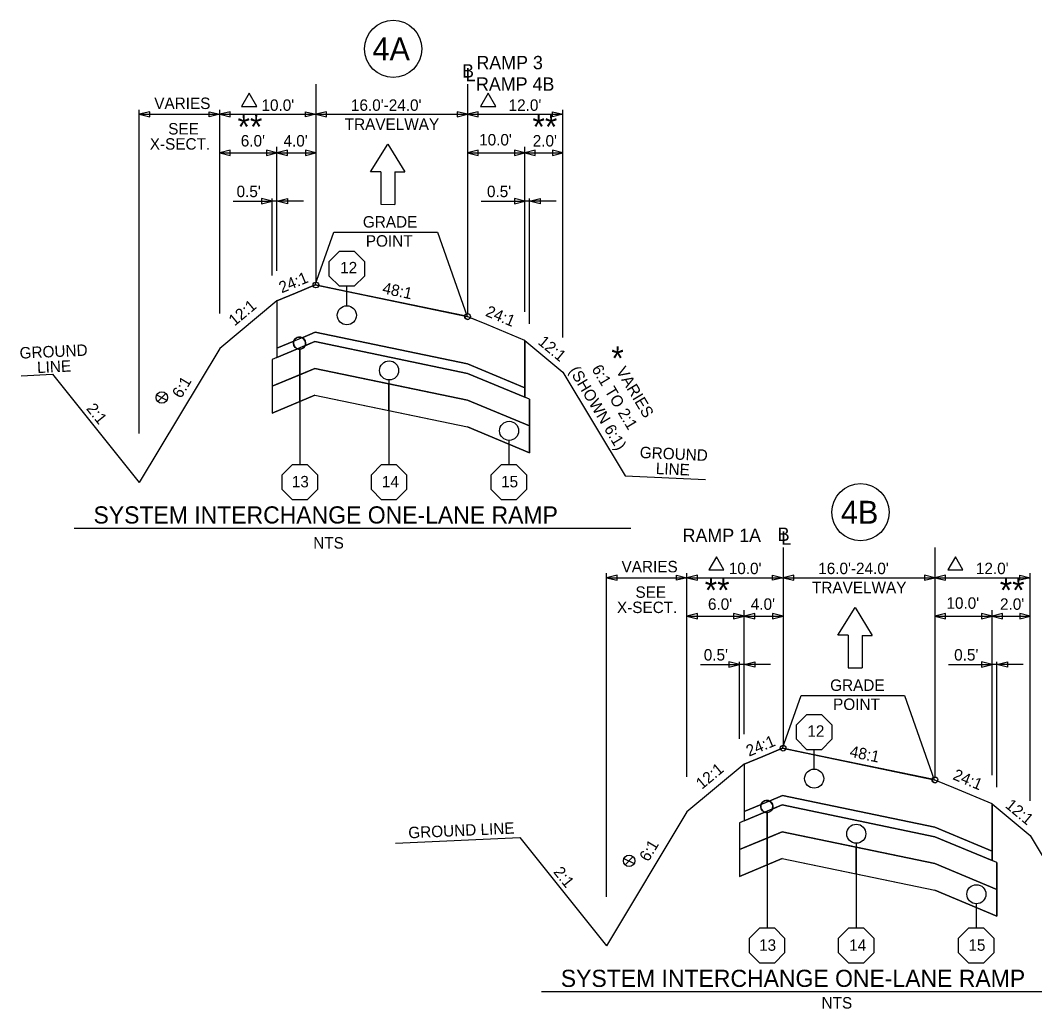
# Model space of a CAD drawing. Extents: x 4932 to 5887, y 4809 to 5473.
# Drawn here: x 5014.7 to 5121, y 5056.1 to 5159.8 of the extents above; entities that cross this region are included whole.
import ezdxf

# ---------------------------------------------------------------- set-up
doc = ezdxf.new("R2010")
doc.units = 0
for name, color, linetype in [('Level 20', 7, 'Continuous'), ('Level 25', 7, 'Continuous'), ('RD_QTY_Miscl_1', 7, 'Continuous'), ('RD_QTY_Miscl_2', 7, 'Continuous'), ('RD_QTY_Miscl_3', 7, 'Continuous'), ('RD_QTY_Miscl_4', 7, 'Continuous'), ('RD_SHT_Typical', 7, 'Continuous'), ('RD_TX_TypSect', 7, 'Continuous'), ('RD_XS_ExGround', 7, 'Continuous'), ('typical_on', 7, 'Continuous')]:
    doc.layers.add(name, color=color, linetype=linetype)

msp = doc.modelspace()

# ---------------------------------------------------------------- linework, layer by layer
at = {"layer": 'Level 20'}
for p, q in [((5051.37, 5143.89), (5053.2, 5146.8)), ((5053.2, 5146.8), (5054.98, 5143.88)), ((5052.47, 5143.89), (5051.37, 5143.89)), ((5052.47, 5143.89), (5052.47, 5140.49)), ((5053.92, 5143.88), (5054.98, 5143.88)), ((5053.92, 5143.88), (5053.92, 5140.48)), ((5052.47, 5140.49), (5053.92, 5140.48)), ((5100.36, 5095.3), (5102.18, 5098.22)), ((5102.18, 5098.22), (5103.97, 5095.29)), ((5101.45, 5095.3), (5100.36, 5095.3)), ((5101.45, 5095.3), (5101.45, 5091.9)), ((5102.91, 5095.29), (5103.97, 5095.29)), ((5102.91, 5095.29), (5102.91, 5091.89)), ((5101.45, 5091.9), (5102.91, 5091.89))]:
    msp.add_line(p, q, dxfattribs=at)
at = {"layer": 'Level 25'}
for p, q in [((5045.58, 5132.05), (5047.52, 5137.58)), ((5047.52, 5137.58), (5058.38, 5137.58)), ((5058.38, 5137.58), (5061.49, 5128.73)), ((5094.57, 5083.46), (5096.51, 5089)), ((5096.51, 5089), (5107.37, 5089)), ((5107.37, 5089), (5110.47, 5080.15))]:
    msp.add_line(p, q, dxfattribs=at)
for centre in [(5053.75, 5156.78), (5102.74, 5108.2)]:
    msp.add_circle(centre, 3, dxfattribs=at)
at = {"layer": 'RD_QTY_Miscl_1'}
for p, q in [((5045.58, 5132.05), (5043.5, 5131.18)), ((5043.5, 5131.18), (5041.56, 5130.37)), ((5041.56, 5130.37), (5041.56, 5125.41)), ((5063.55, 5127.87), (5061.82, 5128.59)), ((5067.55, 5126.21), (5063.55, 5127.87)), ((5041.56, 5125.41), (5043.34, 5126.15)), ((5044.19, 5126.5), (5045.58, 5127.08)), ((5045.58, 5127.08), (5061.55, 5123.76)), ((5067.55, 5121.26), (5067.55, 5126.21)), ((5061.55, 5123.76), (5067.55, 5121.26)), ((5092.49, 5082.6), (5090.55, 5081.79)), ((5094.57, 5083.46), (5092.49, 5082.6)), ((5090.55, 5081.79), (5090.55, 5076.82)), ((5112.54, 5079.29), (5110.81, 5080.01)), ((5093.18, 5077.92), (5094.57, 5078.5)), ((5094.57, 5078.5), (5110.54, 5075.17)), ((5116.54, 5077.62), (5112.54, 5079.29)), ((5090.55, 5076.82), (5092.33, 5077.56)), ((5116.54, 5072.67), (5116.54, 5077.62)), ((5110.54, 5075.17), (5116.54, 5072.67))]:
    msp.add_line(p, q, dxfattribs=at)
for points in [[(5061.26, 5128.78), (5048.89, 5131.36), (5045.58, 5132.05)], [(5110.24, 5080.2), (5097.88, 5082.77), (5094.57, 5083.46)]]:
    msp.add_lwpolyline(points, dxfattribs=at)
for centre in [(5048.89, 5128.85), (5097.88, 5080.27)]:
    msp.add_circle(centre, 1, dxfattribs=at)
for centre, radius, start, end in [((5061.55, 5128.72), 0.3, 168.2319, 334.9662), ((5043.93, 5125.93), 0.63, 65.5928, 159.6453), ((5110.54, 5080.14), 0.3, 168.2319, 334.9662), ((5092.92, 5077.35), 0.63, 65.5928, 159.6453)]:
    msp.add_arc(centre, radius, start, end, dxfattribs=at)
at = {"layer": 'RD_QTY_Miscl_2'}
for p, q in [((5043.34, 5126.15), (5041.56, 5125.41)), ((5045.58, 5127.08), (5044.19, 5126.5)), ((5061.55, 5123.76), (5045.58, 5127.08)), ((5041.56, 5125.41), (5041.56, 5124.43)), ((5041.56, 5124.43), (5043.72, 5125.34)), ((5044.5, 5125.66), (5045.55, 5126.1)), ((5045.55, 5126.1), (5061.55, 5122.76)), ((5067.55, 5121.26), (5061.55, 5123.76)), ((5061.55, 5122.76), (5067.55, 5120.27)), ((5067.55, 5120.27), (5067.55, 5121.26)), ((5094.57, 5078.5), (5093.18, 5077.92)), ((5110.54, 5075.17), (5094.57, 5078.5)), ((5092.33, 5077.56), (5090.55, 5076.82)), ((5093.48, 5077.07), (5094.54, 5077.51)), ((5094.54, 5077.51), (5110.54, 5074.18)), ((5090.55, 5076.82), (5090.55, 5075.85)), ((5090.55, 5075.85), (5092.71, 5076.75)), ((5116.54, 5072.67), (5110.54, 5075.17)), ((5110.54, 5074.18), (5116.54, 5071.68)), ((5116.54, 5071.68), (5116.54, 5072.67))]:
    msp.add_line(p, q, dxfattribs=at)
for centre, start, end in [((5043.93, 5125.93), 159.6453, 250.9378), ((5043.93, 5125.93), 334.3019, 65.5928), ((5092.92, 5077.35), 159.6453, 250.9378), ((5092.92, 5077.35), 334.3019, 65.5928)]:
    msp.add_arc(centre, 0.63, start, end, dxfattribs=at)
at = {"layer": 'RD_QTY_Miscl_3'}
for p, q in [((5043.95, 5125.3), (5043.95, 5122.62)), ((5043.95, 5122.62), (5043.95, 5125.3)), ((5045.55, 5126.1), (5044.5, 5125.66)), ((5061.55, 5122.76), (5045.55, 5126.1)), ((5041.06, 5124.23), (5041.06, 5121.41)), ((5043.95, 5122.62), (5045.55, 5123.29)), ((5041.06, 5121.41), (5043.95, 5122.62)), ((5067.55, 5120.27), (5061.55, 5122.76)), ((5061.55, 5119.95), (5068.05, 5117.25)), ((5068.05, 5120.06), (5067.55, 5120.27)), ((5068.05, 5117.25), (5068.05, 5120.06)), ((5094.54, 5077.51), (5093.48, 5077.07)), ((5110.54, 5074.18), (5094.54, 5077.51)), ((5092.94, 5076.72), (5092.94, 5074.03)), ((5092.94, 5074.03), (5092.94, 5076.72)), ((5090.05, 5075.64), (5090.05, 5072.83)), ((5090.05, 5072.83), (5092.94, 5074.03)), ((5092.94, 5074.03), (5094.54, 5074.7)), ((5116.54, 5071.68), (5110.54, 5074.18)), ((5110.54, 5071.37), (5117.04, 5068.66)), ((5117.04, 5071.47), (5116.54, 5071.68)), ((5117.04, 5068.66), (5117.04, 5071.47))]:
    msp.add_line(p, q, dxfattribs=at)
for points in [[(5043.72, 5125.34), (5041.56, 5124.43), (5041.06, 5124.23)], [(5045.55, 5123.29), (5053.3, 5121.67), (5061.55, 5119.95)], [(5068.05, 5117.25), (5068.05, 5117.25)], [(5092.71, 5076.75), (5090.55, 5075.85), (5090.05, 5075.64)], [(5094.54, 5074.7), (5102.29, 5073.09), (5110.54, 5071.37)], [(5117.04, 5068.66), (5117.04, 5068.66)]]:
    msp.add_lwpolyline(points, dxfattribs=at)
for centre in [(5053.32, 5123.07), (5102.3, 5074.49)]:
    msp.add_circle(centre, 1, dxfattribs=at)
for centre, start, end in [((5043.93, 5125.93), 250.9378, 272.146), ((5043.93, 5125.93), 272.146, 334.3019), ((5092.92, 5077.35), 250.9378, 272.146), ((5092.92, 5077.35), 272.146, 334.3019)]:
    msp.add_arc(centre, 0.63, start, end, dxfattribs=at)
at = {"layer": 'RD_QTY_Miscl_4'}
for p, q in [((5045.55, 5123.29), (5043.95, 5122.62)), ((5053.3, 5121.67), (5045.55, 5123.29)), ((5043.95, 5122.62), (5041.06, 5121.41)), ((5043.95, 5122.62), (5043.95, 5119.81)), ((5043.95, 5119.81), (5043.95, 5122.62)), ((5053.3, 5118.86), (5053.3, 5121.67)), ((5061.55, 5119.95), (5053.3, 5121.67)), ((5053.3, 5121.67), (5053.3, 5118.86)), ((5041.06, 5118.6), (5043.95, 5119.81)), ((5043.95, 5119.81), (5045.55, 5120.48)), ((5045.55, 5120.48), (5053.3, 5118.86)), ((5068.05, 5117.25), (5061.55, 5119.95)), ((5053.3, 5118.86), (5061.55, 5117.14)), ((5068.05, 5114.43), (5068.05, 5117.25)), ((5092.94, 5074.03), (5090.05, 5072.83)), ((5094.54, 5074.7), (5092.94, 5074.03)), ((5092.94, 5074.03), (5092.94, 5071.22)), ((5092.94, 5071.22), (5092.94, 5074.03)), ((5102.29, 5073.09), (5094.54, 5074.7)), ((5102.29, 5070.28), (5102.29, 5073.09)), ((5110.54, 5071.37), (5102.29, 5073.09)), ((5102.29, 5073.09), (5102.29, 5070.28)), ((5092.94, 5071.22), (5094.54, 5071.89)), ((5094.54, 5071.89), (5102.29, 5070.28)), ((5090.05, 5070.02), (5092.94, 5071.22)), ((5117.04, 5068.66), (5110.54, 5071.37)), ((5102.29, 5070.28), (5110.54, 5068.56)), ((5117.04, 5065.85), (5117.04, 5068.66))]:
    msp.add_line(p, q, dxfattribs=at)
for points in [[(5041.06, 5121.41), (5041.06, 5121.41), (5041.06, 5118.6)], [(5061.55, 5117.14), (5065.88, 5115.34), (5068.05, 5114.43)], [(5068.05, 5117.25), (5068.05, 5117.25)], [(5090.05, 5072.83), (5090.05, 5072.83), (5090.05, 5070.02)], [(5110.54, 5068.56), (5114.86, 5066.76), (5117.04, 5065.85)], [(5117.04, 5068.66), (5117.04, 5068.66)]]:
    msp.add_lwpolyline(points, dxfattribs=at)
for centre in [(5065.9, 5116.74), (5114.89, 5068.15)]:
    msp.add_circle(centre, 1, dxfattribs=at)
at = {"layer": 'RD_SHT_Typical'}
for p, q in [((5043.5, 5131.18), (5045.58, 5132.05)), ((5041.56, 5130.37), (5035.56, 5125.38)), ((5041.56, 5130.37), (5043.5, 5131.18)), ((5041.56, 5130.37), (5041.56, 5124.43)), ((5063.55, 5127.87), (5061.49, 5128.73)), ((5067.55, 5126.21), (5063.55, 5127.87)), ((5041.56, 5125.41), (5045.58, 5127.08)), ((5067.55, 5126.21), (5067.55, 5120.27)), ((5067.55, 5126.21), (5071.55, 5122.88)), ((5035.56, 5125.38), (5027.13, 5111.32)), ((5045.55, 5126.1), (5041.05, 5124.22)), ((5041.06, 5124.23), (5041.06, 5118.6)), ((5045.55, 5123.29), (5041.05, 5121.41)), ((5067.55, 5121.26), (5061.55, 5123.76)), ((5018.04, 5122.67), (5027.13, 5111.32)), ((5068.05, 5120.06), (5061.55, 5122.76)), ((5071.55, 5122.88), (5078.07, 5112.01)), ((5045.55, 5120.48), (5041.06, 5118.6)), ((5068.05, 5117.25), (5061.55, 5119.95)), ((5068.05, 5120.06), (5068.05, 5114.43)), ((5068.05, 5114.43), (5061.55, 5117.14)), ((5090.55, 5081.79), (5092.49, 5082.6)), ((5092.49, 5082.6), (5094.57, 5083.46)), ((5090.55, 5081.79), (5084.55, 5076.79)), ((5090.55, 5081.79), (5090.55, 5075.85)), ((5112.54, 5079.29), (5110.47, 5080.15)), ((5090.55, 5076.82), (5094.57, 5078.5)), ((5116.54, 5077.62), (5112.54, 5079.29)), ((5094.54, 5077.51), (5090.04, 5075.64)), ((5116.54, 5077.62), (5116.54, 5071.68)), ((5116.54, 5077.62), (5120.54, 5074.29)), ((5084.55, 5076.79), (5076.11, 5062.73)), ((5090.05, 5075.64), (5090.05, 5070.02)), ((5116.54, 5072.67), (5110.54, 5075.17)), ((5067.03, 5074.09), (5076.11, 5062.73)), ((5094.54, 5074.7), (5090.04, 5072.83)), ((5117.04, 5071.47), (5110.54, 5074.18)), ((5120.54, 5074.29), (5128.02, 5061.81)), ((5094.54, 5071.89), (5090.05, 5070.02)), ((5117.04, 5068.66), (5110.54, 5071.37)), ((5117.04, 5071.47), (5117.04, 5065.85)), ((5117.04, 5065.85), (5110.54, 5068.56))]:
    msp.add_line(p, q, dxfattribs=at)
for points in [[(5045.58, 5132.05), (5061.49, 5128.73)], [(5045.58, 5127.08), (5061.55, 5123.76)], [(5045.55, 5126.1), (5061.55, 5122.76)], [(5045.55, 5123.29), (5061.55, 5119.95)], [(5045.55, 5120.48), (5061.55, 5117.14)], [(5094.57, 5083.46), (5110.47, 5080.15)], [(5094.57, 5078.5), (5110.54, 5075.17)], [(5094.54, 5077.51), (5110.54, 5074.18)], [(5094.54, 5074.7), (5110.54, 5071.37)], [(5094.54, 5071.89), (5110.54, 5068.56)]]:
    msp.add_lwpolyline(points, dxfattribs=at)
at = {"layer": 'RD_TX_TypSect'}
for p, q in [((5045.65, 5153.1), (5045.65, 5132.4)), ((5061.55, 5153.1), (5061.55, 5129.08)), ((5027.13, 5116.46), (5027.13, 5150.41)), ((5027.13, 5149.93), (5035.56, 5149.93)), ((5035.56, 5129.05), (5035.56, 5150.41)), ((5035.56, 5149.93), (5045.65, 5149.93)), ((5045.65, 5149.93), (5061.55, 5149.93)), ((5061.55, 5149.93), (5071.55, 5149.93)), ((5071.55, 5126.52), (5071.55, 5150.41)), ((5041.56, 5133.5), (5041.56, 5146.51)), ((5067.55, 5129.23), (5067.55, 5146.51)), ((5035.56, 5145.89), (5041.56, 5145.89)), ((5041.56, 5145.89), (5045.65, 5145.89)), ((5061.55, 5145.89), (5067.55, 5145.89)), ((5067.55, 5145.89), (5071.55, 5145.89)), ((5041.06, 5133.02), (5041.06, 5141.09)), ((5068.05, 5127.96), (5068.05, 5141.09)), ((5036.98, 5140.81), (5041.06, 5140.81)), ((5044.33, 5140.81), (5041.06, 5140.81)), ((5062.96, 5140.81), (5067.55, 5140.81)), ((5070.82, 5140.81), (5067.55, 5140.81)), ((5048.89, 5129.85), (5048.89, 5131.89)), ((5043.95, 5125.3), (5043.95, 5113.2)), ((5053.3, 5122.07), (5053.3, 5113.2)), ((5028.95, 5120.5), (5030.03, 5119.95)), ((5029.08, 5119.81), (5029.9, 5120.65)), ((5065.88, 5115.74), (5065.88, 5113.2)), ((5020.31, 5106.53), (5078.67, 5106.53)), ((5094.63, 5104.51), (5094.63, 5083.81)), ((5110.54, 5104.51), (5110.54, 5080.5)), ((5076.11, 5067.88), (5076.11, 5101.83)), ((5084.55, 5080.46), (5084.55, 5101.83)), ((5120.54, 5077.93), (5120.54, 5101.83)), ((5076.11, 5101.34), (5084.55, 5101.34)), ((5084.55, 5101.34), (5094.63, 5101.34)), ((5094.63, 5101.34), (5110.54, 5101.34)), ((5110.54, 5101.34), (5120.54, 5101.34)), ((5090.55, 5084.92), (5090.55, 5097.92)), ((5116.54, 5080.64), (5116.54, 5097.92)), ((5084.55, 5097.31), (5090.55, 5097.31)), ((5090.55, 5097.31), (5094.63, 5097.31)), ((5110.54, 5097.31), (5116.54, 5097.31)), ((5116.54, 5097.31), (5120.54, 5097.31)), ((5085.97, 5092.23), (5090.05, 5092.23)), ((5090.05, 5084.43), (5090.05, 5092.5)), ((5093.31, 5092.23), (5090.05, 5092.23)), ((5111.95, 5092.23), (5116.54, 5092.23)), ((5119.8, 5092.23), (5116.54, 5092.23)), ((5117.04, 5079.38), (5117.04, 5092.5)), ((5097.88, 5081.27), (5097.88, 5083.3)), ((5092.94, 5076.72), (5092.94, 5064.62)), ((5102.29, 5073.49), (5102.29, 5064.62)), ((5077.94, 5071.91), (5079.01, 5071.37)), ((5078.06, 5071.22), (5078.89, 5072.06)), ((5114.86, 5067.16), (5114.86, 5064.62)), ((5069.29, 5057.95), (5127.66, 5057.95))]:
    msp.add_line(p, q, dxfattribs=at)
for points in [[(5038.64, 5152.13), (5037.84, 5150.74), (5039.44, 5150.74)], [(5063.7, 5152.13), (5062.9, 5150.74), (5064.5, 5150.74)], [(5028.23, 5149.65), (5028.23, 5150.2), (5027.13, 5149.93)], [(5034.46, 5149.65), (5034.46, 5150.2), (5035.56, 5149.93)], [(5036.66, 5149.65), (5036.66, 5150.2), (5035.56, 5149.93)], [(5044.54, 5149.65), (5044.54, 5150.2), (5045.65, 5149.93)], [(5046.75, 5149.65), (5046.75, 5150.2), (5045.65, 5149.93)], [(5060.45, 5150.2), (5060.45, 5149.65), (5061.55, 5149.93)], [(5062.66, 5149.65), (5062.66, 5150.2), (5061.55, 5149.93)], [(5070.45, 5149.65), (5070.45, 5150.2), (5071.55, 5149.93)], [(5036.66, 5145.62), (5036.66, 5146.17), (5035.56, 5145.89)], [(5040.46, 5146.17), (5040.46, 5145.62), (5041.56, 5145.89)], [(5042.66, 5145.62), (5042.66, 5146.17), (5041.56, 5145.89)], [(5044.54, 5146.17), (5044.54, 5145.62), (5045.65, 5145.89)], [(5062.66, 5145.62), (5062.66, 5146.17), (5061.55, 5145.89)], [(5066.45, 5146.17), (5066.45, 5145.62), (5067.55, 5145.89)], [(5068.65, 5145.62), (5068.65, 5146.17), (5067.55, 5145.89)], [(5070.45, 5146.17), (5070.45, 5145.62), (5071.55, 5145.89)], [(5039.96, 5141.09), (5039.96, 5140.54), (5041.06, 5140.81)], [(5042.66, 5141.09), (5042.66, 5140.54), (5041.56, 5140.81)], [(5066.45, 5141.09), (5066.45, 5140.54), (5067.55, 5140.81)], [(5069.15, 5141.09), (5069.15, 5140.54), (5068.05, 5140.81)], [(5087.63, 5103.54), (5086.83, 5102.16), (5088.43, 5102.16)], [(5112.69, 5103.54), (5111.89, 5102.16), (5113.48, 5102.16)], [(5077.22, 5101.07), (5077.22, 5101.62), (5076.11, 5101.34)], [(5083.45, 5101.07), (5083.45, 5101.62), (5084.55, 5101.34)], [(5085.65, 5101.07), (5085.65, 5101.62), (5084.55, 5101.34)], [(5093.53, 5101.07), (5093.53, 5101.62), (5094.63, 5101.34)], [(5095.74, 5101.07), (5095.74, 5101.62), (5094.63, 5101.34)], [(5109.44, 5101.62), (5109.44, 5101.07), (5110.54, 5101.34)], [(5111.64, 5101.07), (5111.64, 5101.62), (5110.54, 5101.34)], [(5119.43, 5101.07), (5119.43, 5101.62), (5120.54, 5101.34)], [(5085.65, 5097.03), (5085.65, 5097.58), (5084.55, 5097.31)], [(5089.44, 5097.58), (5089.44, 5097.03), (5090.55, 5097.31)], [(5091.65, 5097.03), (5091.65, 5097.58), (5090.55, 5097.31)], [(5093.53, 5097.58), (5093.53, 5097.03), (5094.63, 5097.31)], [(5111.64, 5097.03), (5111.64, 5097.58), (5110.54, 5097.31)], [(5115.43, 5097.58), (5115.43, 5097.03), (5116.54, 5097.31)], [(5117.64, 5097.03), (5117.64, 5097.58), (5116.54, 5097.31)], [(5119.43, 5097.58), (5119.43, 5097.03), (5120.54, 5097.31)], [(5088.94, 5092.5), (5088.94, 5091.95), (5090.05, 5092.23)], [(5091.65, 5092.5), (5091.65, 5091.95), (5090.55, 5092.23)], [(5115.43, 5092.5), (5115.43, 5091.95), (5116.54, 5092.23)], [(5118.14, 5092.5), (5118.14, 5091.95), (5117.04, 5092.23)]]:
    msp.add_lwpolyline(points, close=True, dxfattribs=at)
for centre, radius in [((5045.65, 5132.03), 0.3), ((5048.89, 5128.85), 1), ((5061.55, 5128.72), 0.3), ((5043.93, 5125.93), 0.63), ((5053.32, 5123.07), 1), ((5029.5, 5120.23), 0.6), ((5065.9, 5116.74), 1), ((5094.63, 5083.45), 0.3), ((5097.88, 5080.27), 1), ((5110.54, 5080.14), 0.3), ((5092.92, 5077.35), 0.63), ((5102.3, 5074.49), 1), ((5078.48, 5071.65), 0.6), ((5114.89, 5068.15), 1)]:
    msp.add_circle(centre, radius, dxfattribs=at)
at = {"layer": 'RD_XS_ExGround'}
for p, q in [((5014.75, 5122.52), (5018.04, 5122.67)), ((5078.07, 5112.01), (5086.5, 5111.63)), ((5054, 5073.49), (5067.03, 5074.09))]:
    msp.add_line(p, q, dxfattribs=at)
at = {"layer": 'typical_on'}
for points in [[(5050.74, 5134.5), (5050.74, 5132.97), (5049.66, 5131.89), (5048.13, 5131.89), (5047.04, 5132.97), (5047.04, 5134.5), (5048.13, 5135.58), (5049.66, 5135.58)], [(5045.8, 5112.12), (5045.8, 5110.59), (5044.72, 5109.51), (5043.19, 5109.51), (5042.11, 5110.59), (5042.11, 5112.12), (5043.19, 5113.2), (5044.72, 5113.2)], [(5055.15, 5112.12), (5055.15, 5110.59), (5054.07, 5109.51), (5052.54, 5109.51), (5051.46, 5110.59), (5051.46, 5112.12), (5052.54, 5113.2), (5054.07, 5113.2)], [(5067.72, 5112.12), (5067.72, 5110.59), (5066.64, 5109.51), (5065.11, 5109.51), (5064.03, 5110.59), (5064.03, 5112.12), (5065.11, 5113.2), (5066.64, 5113.2)], [(5099.72, 5085.92), (5099.72, 5084.39), (5098.64, 5083.3), (5097.11, 5083.3), (5096.03, 5084.39), (5096.03, 5085.92), (5097.11, 5087), (5098.64, 5087)], [(5094.79, 5063.53), (5094.79, 5062), (5093.71, 5060.92), (5092.18, 5060.92), (5091.09, 5062), (5091.09, 5063.53), (5092.18, 5064.62), (5093.71, 5064.62)], [(5104.14, 5063.53), (5104.14, 5062), (5103.05, 5060.92), (5101.52, 5060.92), (5100.44, 5062), (5100.44, 5063.53), (5101.52, 5064.62), (5103.05, 5064.62)], [(5116.71, 5063.53), (5116.71, 5062), (5115.63, 5060.92), (5114.1, 5060.92), (5113.02, 5062), (5113.02, 5063.53), (5114.1, 5064.62), (5115.63, 5064.62)]]:
    msp.add_lwpolyline(points, close=True, dxfattribs=at)

# ---------------------------------------------------------------- texts
at = {"layer": 'Level 25'}
for s, p in [('4A', (5051.58, 5155.58)), ('4B', (5100.69, 5107))]:
    msp.add_text(s, height=2.4, dxfattribs=at).set_placement(p)
at = {"layer": 'RD_TX_TypSect'}
for s, height, p in [('RAMP 3', 1.4, (5062.47, 5154.65)), ('B', 1.4, (5060.97, 5153.78)), ('L', 1.4, (5061.35, 5153.39)), ('RAMP 4B', 1.4, (5062.43, 5152.4)), ('VARIES', 1.2, (5028.7, 5150.48)), ("10.0'", 1.2, (5039.94, 5150.29)), ("16.0'-24.0'", 1.2, (5049.32, 5150.29)), ("12.0'", 1.2, (5065.85, 5150.29)), ('**', 2.5, (5037.43, 5147.37)), ('**', 2.5, (5068.35, 5147.37)), ('SEE', 1.2, (5030.16, 5147.81)), ('TRAVELWAY', 1.2, (5048.67, 5148.29)), ('X-SECT.', 1.2, (5028.23, 5146.22)), ("6.0'", 1.2, (5037.77, 5146.55)), ("4.0'", 1.2, (5042.25, 5146.55)), ("10.0'", 1.2, (5062.76, 5146.66)), ("2.0'", 1.2, (5068.38, 5146.55)), ("0.5'", 1.2, (5037.33, 5141.24)), ("0.5'", 1.2, (5063.58, 5141.24)), ('GRADE', 1.2, (5050.57, 5138.05)), ('POINT', 1.2, (5050.88, 5136.05)), ('12', 1.2, (5048.19, 5133.25)), ('*', 2.5, (5076.62, 5123.1)), ('13', 1.2, (5043.12, 5110.81)), ('14', 1.2, (5052.57, 5110.81)), ('15', 1.2, (5065.06, 5110.81)), ('SYSTEM INTERCHANGE ONE-LANE RAMP', 1.8, (5022.33, 5107.02)), ('RAMP 1A', 1.4, (5084.09, 5105.08)), ('B', 1.4, (5094.06, 5105.19)), ('L', 1.4, (5094.43, 5104.8)), ('NTS', 1.2, (5045.37, 5104.39)), ('VARIES', 1.2, (5077.69, 5101.9)), ("10.0'", 1.2, (5088.93, 5101.71)), ("16.0'-24.0'", 1.2, (5098.31, 5101.71)), ("12.0'", 1.2, (5114.84, 5101.71)), ('**', 2.5, (5086.41, 5098.78)), ('TRAVELWAY', 1.2, (5097.66, 5099.71)), ('**', 2.5, (5117.34, 5098.78)), ('SEE', 1.2, (5079.15, 5099.23)), ('X-SECT.', 1.2, (5077.21, 5097.63)), ("6.0'", 1.2, (5086.75, 5097.97)), ("4.0'", 1.2, (5091.24, 5097.97)), ("10.0'", 1.2, (5111.75, 5098.08)), ("2.0'", 1.2, (5117.37, 5097.97)), ("0.5'", 1.2, (5086.31, 5092.65)), ("0.5'", 1.2, (5112.56, 5092.65)), ('GRADE', 1.2, (5099.56, 5089.47)), ('POINT', 1.2, (5099.87, 5087.47)), ('12', 1.2, (5097.17, 5084.66)), ('13', 1.2, (5092.11, 5062.22)), ('14', 1.2, (5101.56, 5062.22)), ('15', 1.2, (5114.05, 5062.22)), ('SYSTEM INTERCHANGE ONE-LANE RAMP', 1.8, (5071.32, 5058.43)), ('NTS', 1.2, (5098.66, 5056.16))]:
    msp.add_text(s, height=height, dxfattribs=at).set_placement(p)
for s, rotation, p in [('24:1', 22.619, (5042.07, 5131.15)), ('48:1', 348.2317, (5052.55, 5131.16)), ('12:1', 39.8056, (5037.12, 5127.67)), ('24:1', 337.3801, (5063.34, 5128.82)), ('12:1', 320.1939, (5068.84, 5125.91)), ('GROUND', 2.6095, (5014.61, 5124.3)), ('LINE', 2.6095, (5016.44, 5122.79)), ('(SHOWN 6:1)', 300.9638, (5072.15, 5123.07)), ('6:1 TO 2:1', 300.9638, (5074.51, 5123.23)), ('VARIES', 300.9638, (5077.08, 5123.02)), ('6:1', 59.0362, (5031.51, 5120.06)), ('2:1', 308.6598, (5021.51, 5119.05)), ('GROUND', 357.3905, (5079.58, 5113.89)), ('LINE', 357.3905, (5081.26, 5112.21)), ('24:1', 22.619, (5091.05, 5082.56)), ('48:1', 348.2317, (5101.54, 5082.58)), ('12:1', 39.8056, (5086.11, 5079.09)), ('24:1', 337.3801, (5112.33, 5080.23)), ('12:1', 320.1939, (5117.83, 5077.32)), ('GROUND LINE', 2.6095, (5055.36, 5074)), ('6:1', 59.0362, (5080.5, 5071.48)), ('2:1', 308.6598, (5070.49, 5070.46))]:
    msp.add_text(s, height=1.2, rotation=rotation, dxfattribs=at).set_placement(p)

doc.saveas('drawing.dxf')
